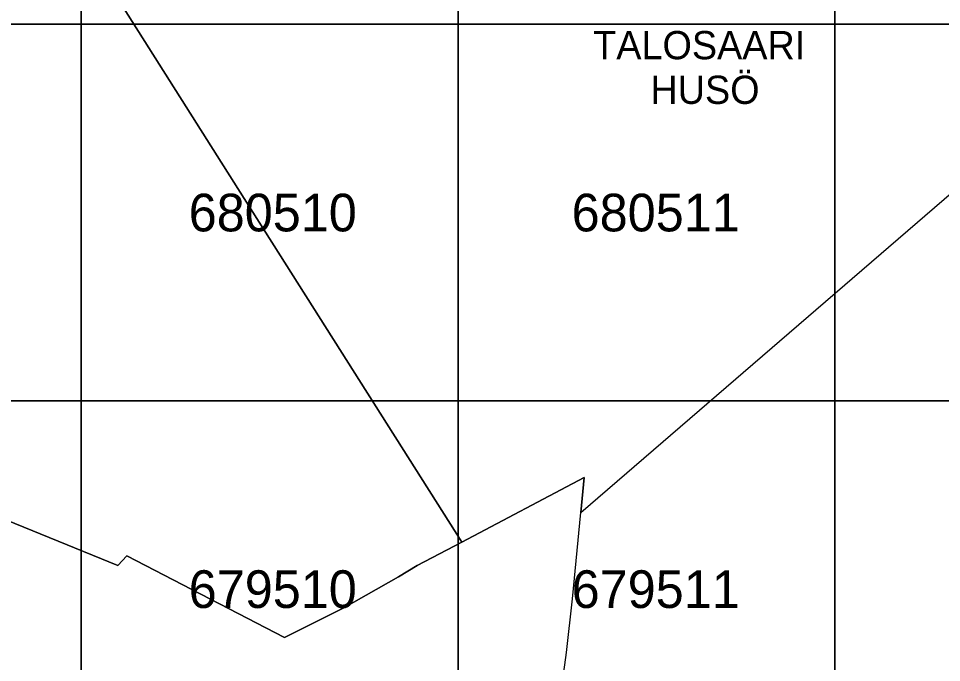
# Model space of a CAD drawing. Extents: x 25485000 to 25520000, y 6656775 to 6690000.
# Drawn here: x 25509833 to 25512283, y 6679305 to 6681015 of the extents above; entities that cross this region are included whole.
import ezdxf

# ---------------------------------------------------------------- set-up
doc = ezdxf.new("R2010")
doc.units = 0
doc.layers.add('Level 63', color=7, linetype='Continuous')

msp = doc.modelspace()

# ---------------------------------------------------------------- linework, layer by layer
at = {"layer": 'Level 63'}
for points in [[(25509000, 6681000), (25510000, 6681000), (25510000, 6682000), (25509000, 6682000)], [(25510000, 6681000), (25511000, 6681000), (25511000, 6682000), (25510000, 6682000)], [(25511000, 6681000), (25512000, 6681000), (25512000, 6682000), (25511000, 6682000)], [(25512000, 6681000), (25513000, 6681000), (25513000, 6682000), (25512000, 6682000)], [(25509000, 6680000), (25510000, 6680000), (25510000, 6681000), (25509000, 6681000)], [(25510000, 6680000), (25511000, 6680000), (25511000, 6681000), (25510000, 6681000)], [(25511000, 6680000), (25512000, 6680000), (25512000, 6681000), (25511000, 6681000)], [(25512000, 6680000), (25513000, 6680000), (25513000, 6681000), (25512000, 6681000)], [(25509000, 6679000), (25510000, 6679000), (25510000, 6680000), (25509000, 6680000)], [(25510000, 6679000), (25511000, 6679000), (25511000, 6680000), (25510000, 6680000)], [(25511000, 6679000), (25512000, 6679000), (25512000, 6680000), (25511000, 6680000)], [(25512000, 6679000), (25513000, 6679000), (25513000, 6680000), (25512000, 6680000)]]:
    msp.add_lwpolyline(points, close=True, dxfattribs=at)
for points in [[(25509256.4, 6679905), (25510096.8, 6679562.8), (25510121, 6679588.2), (25510539.5, 6679371.7), (25510696.9, 6679450.1), (25510842.1, 6679533.1), (25510891.7, 6679562.6), (25511009.8, 6679625), (25510996.4, 6679646.1), (25510431.9, 6680537.6), (25509980.7, 6681251.3)], [(25509980.7, 6681251.3), (25510431.9, 6680537.6), (25510996.4, 6679646.1), (25511009.8, 6679625), (25511334.4, 6679796.6), (25511325.7, 6679703.9), (25512554.5, 6680763)], [(25512224.3, 6676346.7), (25511165.3, 6678400.9), (25511257.6, 6679109.3), (25511288, 6679331.7), (25511304.1, 6679474.4), (25511325.7, 6679703.9), (25511334.4, 6679796.6), (25511009.8, 6679625), (25510891.7, 6679562.6), (25510842.1, 6679533.1), (25510696.9, 6679450.1), (25510539.5, 6679371.7), (25510121, 6679588.2), (25510096.8, 6679562.8), (25509256.4, 6679905)]]:
    msp.add_lwpolyline(points, dxfattribs=at)

# ---------------------------------------------------------------- texts
for s, height, p in [('TALOSAARI', 75, (25511358.8, 6680907.1)), ('HUSÖ', 75, (25511510.7, 6680788.5)), ('680510', 100, (25510285.1, 6680450)), ('680511', 100, (25511301.6, 6680450)), ('679510', 100, (25510285.1, 6679450)), ('679511', 100, (25511301.6, 6679450))]:
    msp.add_text(s, height=height, dxfattribs=at).set_placement(p)

doc.saveas('drawing.dxf')
